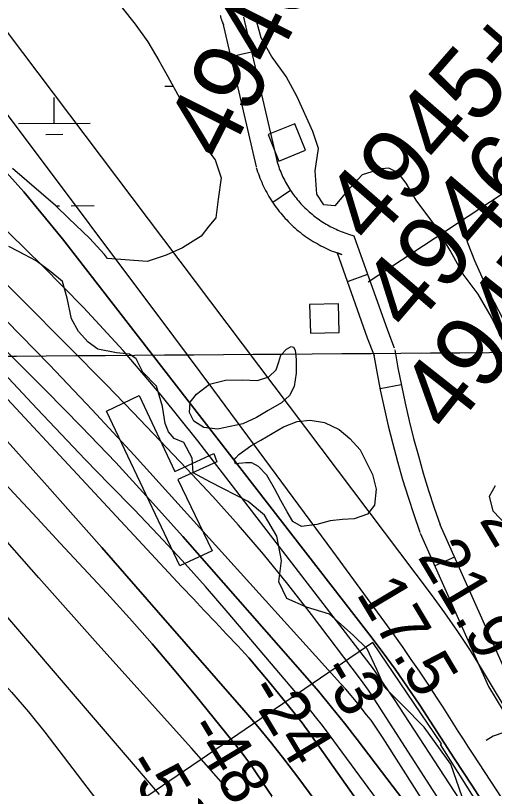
# Model space of a CAD drawing. Extents: x 3540316 to 3578335, y 553172 to 578787.
# Drawn here: x 3551683 to 3552350, y 564084 to 565162 of the extents above; entities that cross this region are included whole.
import ezdxf

# ---------------------------------------------------------------- set-up
doc = ezdxf.new("R2010")
doc.units = 0
for name, color, linetype in [('V-BLDG-OTLN', 7, 'Continuous'), ('V-CHAN-DOCK', 7, 'Continuous'), ('V-GRID-MAJR', 7, 'Continuous'), ('V-RIVR-EDGE', 7, 'Continuous'), ('V-RIVR-RANG', 7, 'Continuous'), ('V-ROAD-CNTR', 7, 'Continuous'), ('V-RRAP-RVMT', 7, 'Continuous'), ('V-SITE-VEGE', 7, 'Continuous'), ('V-SURV-IDEN', 7, 'Continuous'), ('V-TOPO-DPTH', 7, 'Continuous'), ('V-TOPO-MAJR', 7, 'Continuous'), ('V-TOPO-MINR', 7, 'Continuous'), ('V-TOPO-SHOR', 7, 'Continuous'), ('V-TOPO-WATR', 7, 'Continuous'), ('V-WETL-SWMP', 7, 'Continuous')]:
    doc.layers.add(name, color=color, linetype=linetype)

msp = doc.modelspace()

# ---------------------------------------------------------------- linework, layer by layer
at = {"layer": 'V-BLDG-OTLN'}
for points in [[(3552086.8, 564974.5), (3552071.7, 565011.5), (3552034.7, 564996.5), (3552049.7, 564959.4)], [(3552133.6, 564720.1), (3552132.6, 564760.1), (3552092.6, 564759.2), (3552093.6, 564719.2)]]:
    msp.add_lwpolyline(points, close=True, dxfattribs=at)
at = {"layer": 'V-CHAN-DOCK'}
msp.add_lwpolyline([(3551963.3, 564539.5), (3551909, 564515), (3551956.7, 564415.5), (3551911.4, 564394.6), (3551809.4, 564610.6), (3551855, 564632.1), (3551904.7, 564526.1), (3551959, 564551.2), (3551963.3, 564539.5)], dxfattribs=at)
at = {"layer": 'V-GRID-MAJR'}
msp.add_spline([(3544475.4, 564634.2), (3549748.1, 564672.9), (3555020.8, 564712.4), (3560293.6, 564752.7), (3565566.3, 564793.7), (3570839, 564835.5), (3576111.7, 564878.1)], degree=3, dxfattribs=at)
at = {"layer": 'V-RIVR-EDGE'}
msp.add_lwpolyline([(3552305.1, 564072.4), (3552289.3, 564117.8), (3552252.1, 564169.4), (3552222.7, 564199.5), (3552197, 564225.3), (3552186.1, 564249.8), (3552172.7, 564278.7), (3552153.1, 564297.7), (3552120.1, 564327.2), (3552088.3, 564337.1), (3552060.7, 564348.8), (3552049.7, 564372.1), (3552053.5, 564402.1), (3552046.8, 564435.8), (3552029.8, 564465.3), (3552007.1, 564484.3), (3551954.5, 564511.4), (3551930, 564524.3), (3551928.8, 564544.6), (3551917.3, 564566.7), (3551903.8, 564572.2), (3551895.9, 564581.4), (3551891, 564593.1), (3551887.4, 564617), (3551878.9, 564645.2), (3551859.9, 564664.8), (3551850.8, 564683.2), (3551841.6, 564690), (3551823.2, 564691.9), (3551797.5, 564696.8), (3551784, 564706.7), (3551770.6, 564721.4), (3551760.8, 564739.2), (3551754.8, 564768), (3551748.1, 564791.3), (3551731.6, 564804.8), (3551711.4, 564820.2), (3551686.9, 564833.1), (3551673.5, 564839.9)], dxfattribs=at)
at = {"layer": 'V-RIVR-RANG'}
msp.add_line((3552858.7, 565242), (3552174.3, 564790.2), dxfattribs=at)
at = {"layer": 'V-ROAD-CNTR'}
for p, q in [((3552011.7, 565111.4), (3551982.5, 565104.6)), ((3552066.1, 564918.1), (3552041.2, 564901.3)), ((3552173.3, 564801), (3552145.1, 564791)), ((3552220.2, 564647.1), (3552190.8, 564641.3)), ((3552294.6, 564406.6), (3552267.2, 564394.4))]:
    msp.add_line(p, q, dxfattribs=at)
for points in [[(3551968, 565162.7), (3551968.1, 565161.9), (3551968.3, 565161), (3551968.5, 565160.2), (3551968.7, 565159.4), (3551969, 565158.6), (3551969.2, 565157.8), (3551969.5, 565157), (3551969.8, 565156.2), (3551970.1, 565155.4), (3551970.4, 565154.5), (3551970.7, 565153.8), (3551971, 565153), (3551971.3, 565152.3), (3551971.7, 565151.5), (3551972.1, 565150.7), (3551972.4, 565150), (3551972.6, 565149.6)], [(3552000.5, 565160.1), (3552047.2, 564958.2)], [(3551971.2, 565153.4), (3552017.9, 564951.4)], [(3552046.9, 564959.1), (3552047.7, 564956.5), (3552048.5, 564954), (3552049.4, 564951.5), (3552050.3, 564949), (3552051.2, 564946.6), (3552052.2, 564944.1), (3552053.3, 564941.6), (3552054.3, 564939.3), (3552055.4, 564936.9), (3552056.6, 564934.5), (3552057.8, 564932.1), (3552059.1, 564929.7), (3552060.3, 564927.5), (3552061.7, 564925.2), (3552063, 564922.9), (3552064.4, 564920.7), (3552065.9, 564918.4), (3552067.3, 564916.3), (3552068.9, 564914.1), (3552070.4, 564911.9), (3552072, 564909.8), (3552073.6, 564907.8), (3552075.3, 564905.7), (3552077, 564903.7), (3552078.7, 564901.7), (3552080.5, 564899.7), (3552082.3, 564897.7), (3552084.2, 564895.9), (3552086, 564894), (3552088, 564892.1), (3552089.9, 564890.3), (3552091.8, 564888.6), (3552093.8, 564886.9), (3552095.9, 564885.1), (3552097.9, 564883.5), (3552100, 564881.9), (3552102.1, 564880.3), (3552104.3, 564878.7), (3552106.4, 564877.2), (3552108.6, 564875.7), (3552110.8, 564874.3), (3552113.1, 564872.9), (3552115.4, 564871.5), (3552117.6, 564870.2), (3552120, 564868.9), (3552122.3, 564867.7), (3552124.6, 564866.5), (3552127, 564865.3), (3552129.4, 564864.2), (3552131.8, 564863.1), (3552134.3, 564862.1), (3552136.7, 564861.1), (3552139.2, 564860.1), (3552141.7, 564859.2), (3552144.2, 564858.4), (3552146.8, 564857.5), (3552154.2, 564855.1)], [(3552018.2, 564950.4), (3552019.1, 564947.5), (3552020.1, 564944.4), (3552021.1, 564941.5), (3552022.2, 564938.5), (3552023.3, 564935.5), (3552024.5, 564932.6), (3552025.7, 564929.7), (3552027, 564926.8), (3552028.4, 564923.9), (3552029.8, 564921.1), (3552031.2, 564918.3), (3552032.7, 564915.5), (3552034.2, 564912.7), (3552035.8, 564909.9), (3552037.5, 564907.2), (3552039.1, 564904.6), (3552040.9, 564901.9), (3552042.6, 564899.2), (3552044.5, 564896.6), (3552046.3, 564894.1), (3552048.2, 564891.6), (3552050.2, 564889), (3552052.2, 564886.6), (3552054.2, 564884.2), (3552056.3, 564881.8), (3552058.4, 564879.4), (3552060.6, 564877.1), (3552062.8, 564874.8), (3552065, 564872.6), (3552067.3, 564870.4), (3552069.6, 564868.2), (3552072, 564866.1), (3552074.4, 564864), (3552076.8, 564862), (3552079.2, 564860), (3552081.8, 564858), (3552084.3, 564856.1), (3552086.8, 564854.3), (3552089.4, 564852.4), (3552092.1, 564850.7), (3552094.7, 564848.9), (3552097.4, 564847.3), (3552100.1, 564845.7), (3552102.9, 564844.1), (3552105.7, 564842.5), (3552108.4, 564841.1), (3552111.3, 564839.6), (3552114.1, 564838.2), (3552117, 564836.9), (3552119.9, 564835.6), (3552122.8, 564834.3), (3552125.8, 564833.2), (3552128.7, 564832), (3552131.6, 564831), (3552134.7, 564829.9), (3552137.6, 564829), (3552130.8, 564831.2)], [(3552154.2, 564855.1), (3552200.9, 564723.2), (3552210.4, 564698.8)], [(3552130.8, 564831.2), (3552172.8, 564712.8), (3552182.4, 564687.9)], [(3552211.2, 564695.9), (3552215.5, 564670.9), (3552220.4, 564646.2), (3552225.7, 564621.5), (3552231.4, 564596.8), (3552237.5, 564572.3), (3552244.1, 564548), (3552251, 564523.7), (3552258.4, 564499.6), (3552266.2, 564475.6), (3552274.5, 564451.6), (3552274.7, 564451.2)], [(3552181.6, 564690.8), (3552186, 564665.4), (3552191, 564640.1), (3552196.4, 564615), (3552202.2, 564589.8), (3552208.5, 564564.8), (3552215.2, 564540), (3552222.2, 564515.2), (3552229.8, 564490.5), (3552237.8, 564466.1), (3552246.2, 564441.6), (3552246.4, 564441.1)], [(3552274.2, 564452.3), (3552368.8, 564239.9), (3552449.4, 564106.3)], [(3552246.8, 564440.1), (3552342.1, 564226), (3552427.5, 564084.7)]]:
    msp.add_lwpolyline(points, dxfattribs=at)
at = {"layer": 'V-RRAP-RVMT'}
for p, q in [((3552180.6, 564287.6), (3551855.6, 564065.9)), ((3552276.4, 564146.2), (3552180.6, 564287.6)), ((3552275.2, 564145.4), (3552276.4, 564146.2)), ((3552342.5, 564038.5), (3552275.2, 564145.4))]:
    msp.add_line(p, q, dxfattribs=at)
at = {"layer": 'V-SITE-VEGE'}
for points in [[(3552383.3, 564664.1), (3552346, 564741.3), (3552327.7, 564773.5), (3552306.4, 564801.7), (3552288.6, 564834.4), (3552268.7, 564868.1), (3552241, 564904.6), (3552227.2, 564928.6), (3552215.8, 564942.7), (3552203, 564949.5), (3552192.7, 564948.4), (3552165.8, 564939.9), (3552144.4, 564916.7), (3552127.9, 564897), (3552112.2, 564898.4), (3552102.8, 564913), (3552100.1, 564945.8), (3552104.8, 564976.7), (3552096.8, 565000.6), (3552075.4, 565049), (3552060, 565077.3), (3552039.3, 565105.6), (3552024.9, 565131.4), (3552015.8, 565165.2)], [(3552366.7, 564451.9), (3552348.4, 564470.8), (3552343.4, 564491.9), (3552351.6, 564506.6)]]:
    msp.add_lwpolyline(points, dxfattribs=at)
for points in [[(3552072.6, 564695.3), (3552073.7, 564682.6), (3552073.8, 564663.4), (3552071, 564644.8), (3552064.7, 564632), (3552053.5, 564622.1), (3552034.9, 564611.2), (3552018.4, 564601.3), (3551999.3, 564592.8), (3551964.1, 564585.2), (3551944.9, 564587.6), (3551931.1, 564596.3), (3551925.2, 564608.5), (3551926.1, 564622.7), (3551934.8, 564634), (3551952.8, 564647.9), (3551975.4, 564653.4), (3551998.4, 564654.1), (3552020, 564653.3), (3552035.6, 564658.3), (3552045.8, 564668.1), (3552049.7, 564679), (3552052.5, 564688.3), (3552060.3, 564696.7), (3552066.7, 564700.6), (3552070.1, 564699.7)], [(3551993.7, 564549.7), (3552010.8, 564562), (3552024.5, 564570), (3552056.2, 564588.3), (3552075.2, 564595.8), (3552093.4, 564597.9), (3552113.5, 564594.6), (3552133.6, 564584.9), (3552148.4, 564572.3), (3552162.8, 564556.2), (3552180.1, 564522), (3552185.2, 564501.5), (3552182.9, 564479.4), (3552173.2, 564466.6), (3552154.6, 564460.1), (3552138.4, 564459), (3552121.3, 564457.4), (3552102.7, 564452.4), (3552081.2, 564449.3), (3552069.3, 564456.6), (3552061.4, 564469.8), (3552052.5, 564485.9), (3552043.5, 564502.5), (3552033.1, 564521), (3552021.3, 564533.2), (3552011.9, 564538.5), (3552003.6, 564538.5), (3551989.4, 564536.9), (3551987.4, 564542.3), (3551989.8, 564545.2)]]:
    msp.add_lwpolyline(points, close=True, dxfattribs=at)
at = {"layer": 'V-TOPO-DPTH'}
for points in [[(3551392.8, 565198.5), (3551514.2, 565095.5), (3551577.2, 565038.7), (3551637.5, 564979.4), (3551694.1, 564916.4), (3551748.1, 564851), (3552175.2, 564299.5), (3552193.6, 564275.1), (3552211.6, 564250.5), (3552229, 564225.4), (3552246, 564200), (3552294.7, 564125.5), (3552318.6, 564088.6), (3552342.3, 564051.6)], [(3552220.9, 564070.5), (3552209.1, 564086.2), (3552159, 564152.1), (3552141.3, 564174.9), (3552123.2, 564197.4), (3552104.7, 564219.6), (3552085.9, 564241.5), (3551916, 564435.4), (3551869.5, 564487.3), (3551822.4, 564538.6), (3551774.2, 564589), (3551725.3, 564638.7), (3551720.9, 564643.1), (3551673.9, 564690.2), (3551627.1, 564737.6), (3551580.7, 564785.4), (3551534.5, 564833.4), (3551488.5, 564881.5), (3551442.4, 564929.6), (3551396.3, 564977.7), (3551350.2, 565025.7), (3551240.2, 565140.2), (3551225.6, 565155.1), (3551210.7, 565169.7)], [(3551210.7, 565169.7), (3551225.6, 565155.1), (3551240.2, 565140.2), (3551350.2, 565025.7), (3551396.3, 564977.7), (3551442.4, 564929.6), (3551488.5, 564881.5), (3551534.5, 564833.4), (3551580.7, 564785.4), (3551627.1, 564737.6), (3551673.9, 564690.2), (3551720.9, 564643.1), (3551725.3, 564638.7), (3551774.2, 564589), (3551822.4, 564538.6), (3551869.5, 564487.3), (3551916, 564435.4), (3552085.9, 564241.5), (3552104.7, 564219.6), (3552123.2, 564197.4), (3552141.3, 564174.9), (3552159, 564152.1), (3552209.1, 564086.2), (3552220.9, 564070.5)], [(3552185, 563857.7), (3552014.2, 564111.3), (3552009, 564118.7), (3552003.8, 564126), (3551998.4, 564133.2), (3551992.8, 564140.3), (3551934.1, 564213), (3551903.9, 564249.6), (3551873.2, 564285.9), (3551841.7, 564321.5), (3551809.7, 564356.6), (3551777.3, 564391.4), (3551744.9, 564426.3), (3551712.6, 564461.1), (3551680.3, 564496), (3551592.4, 564590.9), (3551516.2, 564673.3), (3551440, 564755.8), (3551364, 564838.3), (3551287.9, 564920.9), (3551148.2, 565072.8), (3551138.1, 565083.4), (3551127.7, 565093.6), (3551116.9, 565103.5)], [(3551116.9, 565103.5), (3551127.7, 565093.6), (3551138.1, 565083.4), (3551148.2, 565072.8), (3551287.9, 564920.9), (3551364, 564838.3), (3551440, 564755.8), (3551516.2, 564673.3), (3551592.4, 564590.9), (3551680.3, 564496), (3551712.6, 564461.1), (3551744.9, 564426.3), (3551777.3, 564391.4), (3551809.7, 564356.6), (3551841.7, 564321.5), (3551873.2, 564285.9), (3551903.9, 564249.6), (3551934.1, 564213), (3551992.8, 564140.3), (3551998.4, 564133.2), (3552003.8, 564126), (3552009, 564118.7), (3552014.2, 564111.3), (3552185, 563857.7)], [(3552321.1, 563993.7), (3552178.1, 564215.6), (3552174.6, 564220.9), (3552171, 564226.2), (3552167.3, 564231.4), (3552163.5, 564236.5), (3552095.3, 564326.7), (3552062.2, 564369), (3552028.4, 564410.7), (3551993.3, 564451.3), (3551957.4, 564491.3), (3551920.8, 564530.6), (3551883.9, 564569.6), (3551846.7, 564608.4), (3551809.2, 564646.9), (3551756.1, 564701), (3551691.5, 564766), (3551626.2, 564830.2)], [(3552321.1, 563993.7), (3552178.1, 564215.6), (3552174.6, 564220.9), (3552171, 564226.2), (3552167.3, 564231.4), (3552163.5, 564236.5), (3552095.3, 564326.7), (3552062.2, 564369), (3552028.4, 564410.7), (3551993.3, 564451.3), (3551957.4, 564491.3), (3551920.8, 564530.6), (3551883.9, 564569.6), (3551846.7, 564608.4), (3551809.2, 564646.9), (3551756.1, 564701), (3551691.5, 564766), (3551626.2, 564830.2)], [(3551671.1, 564627.4), (3551762.5, 564528.9), (3551914.6, 564365.4), (3551930.1, 564348.8), (3551945.6, 564332.3), (3551961.2, 564315.8), (3551976.9, 564299.4), (3551992.4, 564282.8), (3552007.6, 564266), (3552022.4, 564248.8), (3552036.9, 564231.4), (3552076.9, 564182), (3552080.1, 564177.9), (3552083.4, 564173.7), (3552086.5, 564169.5), (3552089.6, 564165.2), (3552288.7, 563882.7)], [(3552288.7, 563882.7), (3552089.6, 564165.2), (3552086.5, 564169.5), (3552083.4, 564173.7), (3552080.1, 564177.9), (3552076.9, 564182), (3552036.9, 564231.4), (3552022.4, 564248.8), (3552007.6, 564266), (3551992.4, 564282.8), (3551976.9, 564299.4), (3551961.2, 564315.8), (3551945.6, 564332.3), (3551930.1, 564348.8), (3551914.6, 564365.4), (3551762.5, 564528.9), (3551671.1, 564627.4)], [(3551642.8, 564599.9), (3551723, 564510.2), (3551802.8, 564420), (3551882.1, 564329.5), (3552000.8, 564193.4), (3552020.3, 564170.5), (3552039.4, 564147.2), (3552058, 564123.5), (3552076.2, 564099.5), (3552115.6, 564046)], [(3551642.8, 564599.9), (3551723, 564510.2), (3551802.8, 564420), (3551882.1, 564329.5), (3552000.8, 564193.4), (3552020.3, 564170.5), (3552039.4, 564147.2), (3552058, 564123.5), (3552076.2, 564099.5), (3552115.6, 564046)]]:
    msp.add_lwpolyline(points, dxfattribs=at)
at = {"layer": 'V-TOPO-MAJR'}
msp.add_lwpolyline([(3551979.5, 564081.5), (3551962.4, 564101.2), (3551945.2, 564120.7), (3551927.8, 564140.2), (3551797.3, 564285.4), (3551715, 564377.7), (3551633.2, 564470.4), (3551552.1, 564563.7), (3551471.5, 564657.5), (3551116.3, 565074)], dxfattribs=at)
at = {"layer": 'V-TOPO-MINR'}
for points in [[(3552450.7, 564051), (3552413.6, 564114.4), (3552376.1, 564177.7), (3552333.3, 564249.2), (3552316.6, 564276.3), (3552299.3, 564303), (3552281.1, 564329.1), (3552262.3, 564354.8), (3551604.2, 565228.5), (3551581.5, 565257.9), (3551558.3, 565286.8), (3551534.2, 565315.1), (3551509.7, 565343), (3551484.6, 565370.4), (3551459, 565397.3), (3551433, 565423.8), (3551406.5, 565449.9), (3550894.9, 565944.3)], [(3551883.3, 564075.7), (3551559.8, 564452.5), (3551476.1, 564547.8), (3551390.9, 564641.9), (3551303.6, 564733.9), (3551214.9, 564824.6), (3551035.7, 565003.7), (3551035.5, 565003.9), (3551035.1, 565004.3), (3551032.5, 565005.6), (3551030.4, 565006.4), (3550284.8, 565467), (3550274.7, 565472.7), (3550264.3, 565478.1), (3550191.2, 565514.4), (3550184.7, 565517.3), (3550178.1, 565519.9), (3550171.3, 565522.1), (3550164.4, 565523.9), (3549630.9, 565679)], [(3552460.9, 563917), (3552321.3, 564130.6), (3552314.1, 564141.7), (3552307, 564152.8), (3552299.8, 564163.9), (3552292.7, 564175), (3552285.6, 564186.2), (3552278.5, 564197.3), (3552271.4, 564208.4), (3552264.2, 564219.4), (3552256.7, 564230.9), (3552245.6, 564247.6), (3552234.3, 564264.1), (3552222.8, 564280.5), (3552211.1, 564296.8), (3552124.8, 564414.9), (3552069.6, 564490), (3552014.3, 564565), (3551958.8, 564639.8), (3551903.1, 564714.4), (3551433.3, 565341.9)], [(3552315.3, 564047.4), (3552210.8, 564208.1), (3552200.8, 564223.1), (3552190.6, 564237.9), (3552180, 564252.5), (3552169.2, 564266.9), (3551936.9, 564569.1), (3551885.8, 564632.9), (3551832.8, 564695.1), (3551777.3, 564755), (3551720.1, 564813.3), (3551650.1, 564881.7), (3551626.4, 564904.6), (3551602.5, 564927.2), (3551578.2, 564949.4), (3551553.8, 564971.4), (3551529.1, 564993.2), (3551504.4, 565015), (3551479.7, 565036.8), (3551455, 565058.5), (3551282.6, 565210)], [(3552342.3, 564051.6), (3552318.6, 564088.6), (3552294.7, 564125.5), (3552246, 564200), (3552229, 564225.4), (3552211.6, 564250.5), (3552193.6, 564275.1), (3552175.2, 564299.5), (3551748.1, 564851), (3551694.1, 564916.4), (3551637.5, 564979.4), (3551577.2, 565038.7), (3551514.2, 565095.5), (3551392.8, 565198.5)], [(3552248, 563984.7), (3552119.8, 564159.2), (3552110.4, 564171.8), (3552100.9, 564184.1), (3552091.1, 564196.3), (3552081.1, 564208.4), (3551979.2, 564328.9), (3551947.3, 564365.8), (3551914.9, 564402.2), (3551881.6, 564437.9), (3551847.9, 564473.1), (3551813.8, 564508.1), (3551779.9, 564543.1), (3551746.2, 564578.4), (3551712.6, 564613.8), (3551645.3, 564685.3), (3551578.2, 564756.5), (3551511.1, 564827.8), (3551444, 564899.1), (3551377, 564970.4), (3551217.1, 565140.8), (3551208.2, 565150), (3551199.1, 565159.1), (3551189.8, 565168)], [(3552220.9, 564070.5), (3552209.1, 564086.2), (3552159, 564152.1), (3552141.3, 564174.9), (3552123.2, 564197.4), (3552104.7, 564219.6), (3552085.9, 564241.5), (3551916, 564435.4), (3551869.5, 564487.3), (3551822.4, 564538.6), (3551774.2, 564589), (3551725.3, 564638.7), (3551720.9, 564643.1), (3551673.9, 564690.2), (3551627.1, 564737.6), (3551580.7, 564785.4), (3551534.5, 564833.4), (3551488.5, 564881.5), (3551442.4, 564929.6), (3551396.3, 564977.7), (3551350.2, 565025.7), (3551240.2, 565140.2), (3551225.6, 565155.1), (3551210.7, 565169.7)], [(3552185, 563857.7), (3552014.2, 564111.3), (3552009, 564118.7), (3552003.8, 564126), (3551998.4, 564133.2), (3551992.8, 564140.3), (3551934.1, 564213), (3551903.9, 564249.6), (3551873.2, 564285.9), (3551841.7, 564321.5), (3551809.7, 564356.6), (3551777.3, 564391.4), (3551744.9, 564426.3), (3551712.6, 564461.1), (3551680.3, 564496), (3551592.4, 564590.9), (3551516.2, 564673.3), (3551440, 564755.8), (3551364, 564838.3), (3551287.9, 564920.9), (3551148.2, 565072.8), (3551138.1, 565083.4), (3551127.7, 565093.6), (3551116.9, 565103.5)], [(3552290.4, 564916.8), (3552305.3, 564868.3), (3552313.3, 564844.3), (3552322.3, 564820.7), (3552332.4, 564797.6), (3552343.5, 564774.8), (3552482, 564507.2), (3552500.7, 564471.1), (3552519.3, 564435), (3552538, 564398.8), (3552556.7, 564362.7), (3553127.9, 563259.2)], [(3552360.8, 563892.8), (3552194.9, 564154.3), (3552192.2, 564158.5), (3552189.5, 564162.7), (3552186.7, 564166.8), (3552183.9, 564170.9), (3552181, 564175), (3552178.1, 564179), (3552175.1, 564183), (3552172, 564186.9), (3552164.4, 564196.6), (3552157.5, 564205.3), (3552150.4, 564213.8), (3552143.2, 564222.3), (3552135.8, 564230.6), (3551848, 564548.8), (3551789.4, 564612.4), (3551730, 564675.2), (3551669.4, 564736.8)], [(3551116.4, 564684.6), (3551138.3, 564669.2), (3551159.9, 564653.4), (3551181.3, 564637.3), (3551202.4, 564620.9), (3551223.4, 564604.2), (3551244.1, 564587.3), (3551264.7, 564570.2), (3551321.2, 564522.5), (3551362.6, 564488.1), (3551404.3, 564454), (3551446.4, 564420.5), (3551488.9, 564387.4), (3551516.5, 564366.1), (3551545, 564343.4), (3551572.9, 564320.1), (3551600.1, 564295.9), (3551626.7, 564271), (3551652.3, 564245.1), (3551677, 564218.4), (3551700.6, 564190.7), (3551723.4, 564162.3), (3551821, 564034.6)], [(3552288.7, 563882.7), (3552089.6, 564165.2), (3552086.5, 564169.5), (3552083.4, 564173.7), (3552080.1, 564177.9), (3552076.9, 564182), (3552036.9, 564231.4), (3552022.4, 564248.8), (3552007.6, 564266), (3551992.4, 564282.8), (3551976.9, 564299.4), (3551961.2, 564315.8), (3551945.6, 564332.3), (3551930.1, 564348.8), (3551914.6, 564365.4), (3551762.5, 564528.9), (3551671.1, 564627.4)], [(3552115.6, 564046), (3552076.2, 564099.5), (3552058, 564123.5), (3552039.4, 564147.2), (3552020.3, 564170.5), (3552000.8, 564193.4), (3551882.1, 564329.5), (3551802.8, 564420), (3551723, 564510.2), (3551642.8, 564599.9)]]:
    msp.add_lwpolyline(points, dxfattribs=at)
at = {"layer": 'V-TOPO-SHOR'}
msp.add_lwpolyline([(3552622.7, 564206.1), (3552608.4, 564197.5), (3552591.1, 564190.8), (3552571.2, 564184.8), (3552541.5, 564182), (3552508.2, 564179.8), (3552478.5, 564177.3), (3552463.8, 564175.6), (3552440.9, 564176.1), (3552420.3, 564176.9), (3552379.5, 564167.8), (3552348.5, 564156.8), (3552338.6, 564150.8)], dxfattribs=at)
at = {"layer": 'V-TOPO-WATR'}
msp.add_lwpolyline([(3552321.1, 563993.7), (3552178.1, 564215.6), (3552174.6, 564220.9), (3552171, 564226.2), (3552167.3, 564231.4), (3552163.5, 564236.5), (3552095.3, 564326.7), (3552062.2, 564369), (3552028.4, 564410.7), (3551993.3, 564451.3), (3551957.4, 564491.3), (3551920.8, 564530.6), (3551883.9, 564569.6), (3551846.7, 564608.4), (3551809.2, 564646.9), (3551756.1, 564701), (3551691.5, 564766), (3551626.2, 564830.2)], dxfattribs=at)
at = {"layer": 'V-WETL-SWMP'}
for p, q in [((3551831.2, 565173.2), (3551849.2, 565150.3)), ((3551849.2, 565150.3), (3551867.2, 565125.8)), ((3551867.2, 565125.8), (3551882.4, 565099.5)), ((3551882.4, 565099.5), (3551895.1, 565077.4)), ((3551895.1, 565077.4), (3551911.2, 565047.7)), ((3551890.8, 565063.9), (3551902.4, 565064)), ((3551736.6, 565012), (3551736.4, 565048)), ((3551911.2, 565047.7), (3551927.3, 565017.5)), ((3551686.6, 565011.6), (3551786.6, 565012.4)), ((3551927.3, 565017.5), (3551940.1, 564988.7)), ((3551724.7, 564996.5), (3551748.7, 564996.7)), ((3551940.1, 564988.7), (3551961, 564961.2)), ((3551961, 564961.2), (3551969.1, 564935.7)), ((3551738.5, 564897.4), (3551678.4, 564948.8)), ((3551969.1, 564935.7), (3551965, 564906.2)), ((3551965, 564906.2), (3551961.9, 564880.2)), ((3551756.8, 564879), (3551738.5, 564897.4)), ((3551739.2, 564896.8), (3551744.1, 564896.8)), ((3551760.1, 564896.9), (3551792.1, 564897.2)), ((3551961.9, 564880.2), (3551952, 564868.3)), ((3551785.9, 564851.8), (3551756.8, 564879)), ((3551952, 564868.3), (3551941.2, 564854.7)), ((3551806.6, 564829), (3551785.9, 564851.8)), ((3551941.2, 564854.7), (3551915.2, 564838.2)), ((3551915.2, 564838.2), (3551892.8, 564828)), ((3551811, 564823.3), (3551806.6, 564829)), ((3551892.8, 564828), (3551865.9, 564819.3)), ((3551865.9, 564819.3), (3551811, 564823.3))]:
    msp.add_line(p, q, dxfattribs=at)

# ---------------------------------------------------------------- texts
at = {"layer": 'V-RIVR-RANG'}
for s, rotation, p in [('20.5', 300.7883, (3552328, 564458.8)), ('21.9', 300.7883, (3552242.1, 564407.6)), ('17.5', 300.7883, (3552156.5, 564356)), ('-3', 300.7883, (3552104.6, 564247.7)), ('-24', 301.0706, (3552003.8, 564220.7)), ('-48', 301.0706, (3551919.3, 564167.3)), ('-59', 301.0706, (3551832.8, 564117))]:
    msp.add_text(s, height=67, rotation=rotation, dxfattribs=at).set_placement(p)
at = {"layer": 'V-SURV-IDEN'}
for s, rotation, p in [('4940+33.1', 63.1909, (3551975.5, 564955.2)), ('4945+44.2', 48.9049, (3552179.3, 564838.3)), ('4946+63.2', 49.4335, (3552231.5, 564717.3)), ('4947+57.6', 51.678, (3552288.3, 564575.6))]:
    msp.add_text(s, height=100, rotation=rotation, dxfattribs=at).set_placement(p)

doc.saveas('drawing.dxf')
